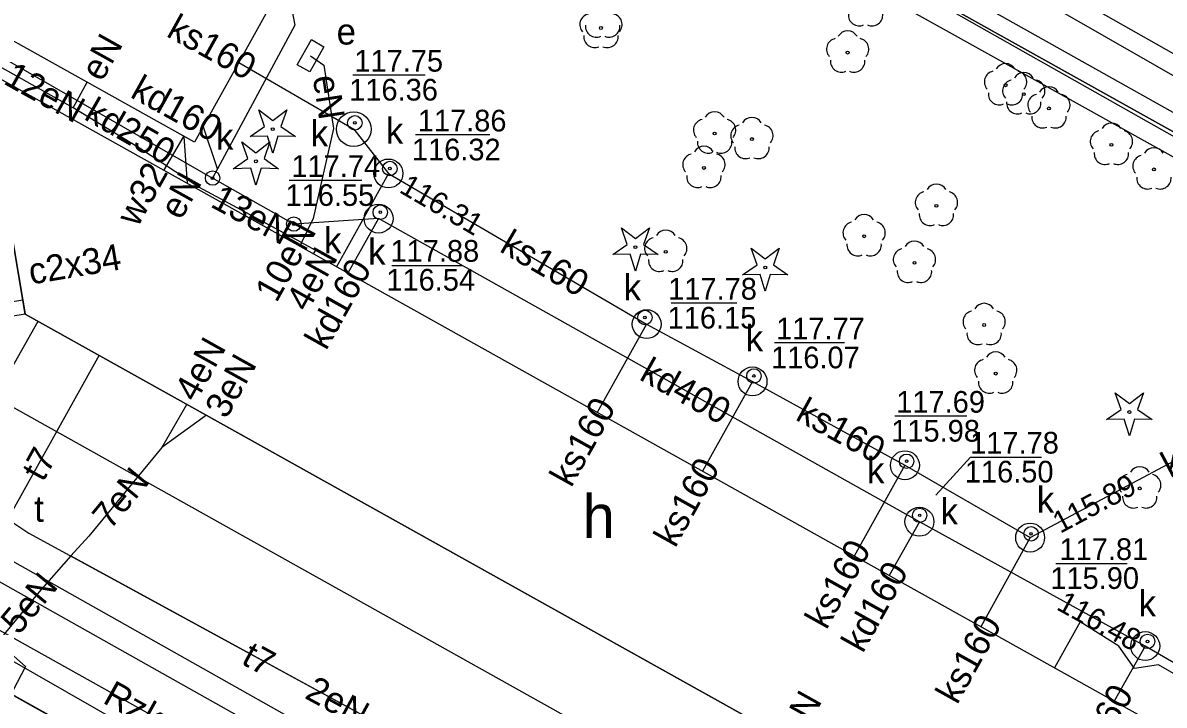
# Model space of a CAD drawing. Extents: x 6434771 to 6436222, y 5663454 to 5664782.
# Drawn here: x 6435316.51 to 6435355.97, y 5663773.05 to 5663796.64 of the extents above; entities that cross this region are included whole.
import ezdxf

# ---------------------------------------------------------------- set-up
doc = ezdxf.new("R2010")
doc.units = 0
for name, color, linetype in [('Warstwa 1', 7, 'Continuous'), ('Warstwa 10', 7, 'Continuous'), ('Warstwa 11', 7, 'Continuous'), ('Warstwa 12', 7, 'Continuous'), ('Warstwa 13', 7, 'Continuous'), ('Warstwa 14', 7, 'Continuous'), ('Warstwa 15', 7, 'Continuous'), ('Warstwa 2', 7, 'Continuous'), ('Warstwa 21', 7, 'Continuous'), ('Warstwa 3', 7, 'Continuous'), ('Warstwa 33', 7, 'Continuous'), ('Warstwa 4', 7, 'Continuous'), ('Warstwa 5', 7, 'Continuous'), ('Warstwa 6', 7, 'Continuous'), ('Warstwa 7', 7, 'Continuous'), ('Warstwa 8', 7, 'Continuous'), ('Warstwa 9', 7, 'Continuous')]:
    doc.layers.add(name, color=color, linetype=linetype)

msp = doc.modelspace()

# ---------------------------------------------------------------- linework, layer by layer
at = {"layer": 'Warstwa 1'}
msp.add_line((6435341.096, 5663801.352), (6435379.471, 5663779.947), dxfattribs=at)
msp.add_line((6435341.096, 5663801.352), (6435379.471, 5663779.947), dxfattribs=at)
for points in [[(6435315.15, 5663804.67), (6435325.88, 5663798.7), (6435322.44, 5663792.51), (6435311.73, 5663798.5), (6435312.37, 5663799.67), (6435312.69, 5663800.25), (6435314.19, 5663802.94), (6435314.51, 5663803.52)], [(6435358.6, 5663770.75), (6435353.88, 5663762.28), (6435350.43, 5663764.21), (6435352.9, 5663768.67), (6435349.4, 5663770.61), (6435348.38, 5663768.83), (6435316.59, 5663786.57), (6435315.32, 5663794.07), (6435315.68, 5663794.72)]]:
    msp.add_lwpolyline(points, close=True, dxfattribs=at)
at = {"layer": 'Warstwa 10'}
for points in [[(6435362.27, 5663788.69), (6435362.41, 5663788.96), (6435362.84, 5663789.86), (6435340.58, 5663802.36), (6435337.82, 5663803.9), (6435320.71, 5663813.64), (6435309.18, 5663820.04), (6435307.2, 5663820.8), (6435302.95, 5663823.03), (6435301.33, 5663824.12), (6435299.2, 5663826.42), (6435293.53, 5663831.99), (6435290.73, 5663834.08), (6435287.63, 5663836.01), (6435276.336, 5663842.501)], [(6435277.98, 5663796.72), (6435309.53, 5663779.08), (6435337.54, 5663763.44)]]:
    msp.add_lwpolyline(points, dxfattribs=at)
for points in [[(6435324.365, 5663792.705), (6435324.867, 5663793.052), (6435324.665, 5663793.628), (6435325.15, 5663793.258), (6435325.635, 5663793.628), (6435325.433, 5663793.052), (6435325.935, 5663792.705), (6435325.325, 5663792.719), (6435325.15, 5663792.135), (6435324.975, 5663792.719)], [(6435323.785, 5663791.595), (6435324.287, 5663791.942), (6435324.085, 5663792.518), (6435324.57, 5663792.148), (6435325.055, 5663792.518), (6435324.853, 5663791.942), (6435325.355, 5663791.595), (6435324.745, 5663791.609), (6435324.57, 5663791.025), (6435324.395, 5663791.609)], [(6435336.905, 5663788.625), (6435337.407, 5663788.972), (6435337.205, 5663789.548), (6435337.69, 5663789.178), (6435338.175, 5663789.548), (6435337.973, 5663788.972), (6435338.475, 5663788.625), (6435337.865, 5663788.639), (6435337.69, 5663788.055), (6435337.515, 5663788.639)], [(6435341.395, 5663787.925), (6435341.897, 5663788.272), (6435341.695, 5663788.848), (6435342.18, 5663788.478), (6435342.665, 5663788.848), (6435342.463, 5663788.272), (6435342.965, 5663787.925), (6435342.355, 5663787.939), (6435342.18, 5663787.355), (6435342.005, 5663787.939)], [(6435353.985, 5663782.925), (6435354.487, 5663783.272), (6435354.285, 5663783.848), (6435354.77, 5663783.478), (6435355.255, 5663783.848), (6435355.053, 5663783.272), (6435355.555, 5663782.925), (6435354.945, 5663782.939), (6435354.77, 5663782.355), (6435354.595, 5663782.939)]]:
    msp.add_lwpolyline(points, close=True, dxfattribs=at)
for centre in [(6435325.15, 5663792.96), (6435324.57, 5663791.85), (6435337.69, 5663788.88), (6435342.18, 5663788.18), (6435354.77, 5663783.18)]:
    msp.add_circle(centre, 0.05, dxfattribs=at)
at = {"layer": 'Warstwa 11'}
for centre in [(6435336.5, 5663796.46), (6435345.03, 5663795.61), (6435350.49, 5663794.48), (6435351.12, 5663794.17), (6435351.99, 5663793.68), (6435340.43, 5663792.81), (6435341.72, 5663792.62), (6435354.15, 5663792.42), (6435340.06, 5663791.62), (6435355.62, 5663791.57), (6435348.1, 5663790.31), (6435345.6, 5663789.26), (6435338.74, 5663788.72), (6435347.34, 5663788.34), (6435349.75, 5663786.19), (6435350.15, 5663784.51), (6435355.13, 5663780.54)]:
    msp.add_circle(centre, 0.05, dxfattribs=at)
for centre, start, end in [((6435336.143, 5663796.576), 102.1471, 221.8529), ((6435336.857, 5663796.576), 318.1471, 77.8529), ((6435345.43, 5663796.907), 174.1471, 293.8529), ((6435345.87, 5663796.907), 246.1471, 5.8529), ((6435336.34, 5663796.517), 174.1471, 293.8529), ((6435336.78, 5663796.517), 246.1471, 5.8529), ((6435336.28, 5663796.157), 174.1471, 293.8529), ((6435336.72, 5663796.157), 246.1471, 5.8529), ((6435345.03, 5663795.985), 30.1471, 149.8529), ((6435344.673, 5663795.726), 102.1471, 221.8529), ((6435345.387, 5663795.726), 318.1471, 77.8529), ((6435344.81, 5663795.307), 174.1471, 293.8529), ((6435345.25, 5663795.307), 246.1471, 5.8529), ((6435350.133, 5663794.596), 102.1471, 221.8529), ((6435350.49, 5663794.855), 30.1471, 149.8529), ((6435350.847, 5663794.596), 318.1471, 77.8529), ((6435350.763, 5663794.286), 102.1471, 221.8529), ((6435351.12, 5663794.545), 30.1471, 149.8529), ((6435351.477, 5663794.286), 318.1471, 77.8529), ((6435350.27, 5663794.177), 174.1471, 293.8529), ((6435350.71, 5663794.177), 246.1471, 5.8529), ((6435351.633, 5663793.796), 102.1471, 221.8529), ((6435351.99, 5663794.055), 30.1471, 149.8529), ((6435352.347, 5663793.796), 318.1471, 77.8529), ((6435350.9, 5663793.867), 174.1471, 293.8529), ((6435351.34, 5663793.867), 246.1471, 5.8529), ((6435340.43, 5663793.185), 30.1471, 149.8529), ((6435341.72, 5663792.995), 30.1471, 149.8529), ((6435351.77, 5663793.377), 174.1471, 293.8529), ((6435352.21, 5663793.377), 246.1471, 5.8529), ((6435340.073, 5663792.926), 102.1471, 221.8529), ((6435340.787, 5663792.926), 318.1471, 77.8529), ((6435341.363, 5663792.736), 102.1471, 221.8529), ((6435342.077, 5663792.736), 318.1471, 77.8529), ((6435354.15, 5663792.795), 30.1471, 149.8529), ((6435353.793, 5663792.536), 102.1471, 221.8529), ((6435354.507, 5663792.536), 318.1471, 77.8529), ((6435340.06, 5663791.995), 30.1471, 149.8529), ((6435340.21, 5663792.507), 174.1471, 293.8529), ((6435340.65, 5663792.507), 246.1471, 5.8529), ((6435341.5, 5663792.317), 174.1471, 293.8529), ((6435341.94, 5663792.317), 246.1471, 5.8529), ((6435355.62, 5663791.945), 30.1471, 149.8529), ((6435339.703, 5663791.736), 102.1471, 221.8529), ((6435340.417, 5663791.736), 318.1471, 77.8529), ((6435353.93, 5663792.117), 174.1471, 293.8529), ((6435354.37, 5663792.117), 246.1471, 5.8529), ((6435355.263, 5663791.686), 102.1471, 221.8529), ((6435339.84, 5663791.317), 174.1471, 293.8529), ((6435340.28, 5663791.317), 246.1471, 5.8529), ((6435348.1, 5663790.685), 30.1471, 149.8529), ((6435355.4, 5663791.267), 174.1471, 293.8529), ((6435355.84, 5663791.267), 246.1471, 5.8529), ((6435347.743, 5663790.426), 102.1471, 221.8529), ((6435348.457, 5663790.426), 318.1471, 77.8529), ((6435345.6, 5663789.635), 30.1471, 149.8529), ((6435347.88, 5663790.007), 174.1471, 293.8529), ((6435348.32, 5663790.007), 246.1471, 5.8529), ((6435338.74, 5663789.095), 30.1471, 149.8529), ((6435345.243, 5663789.376), 102.1471, 221.8529), ((6435345.957, 5663789.376), 318.1471, 77.8529), ((6435338.383, 5663788.836), 102.1471, 221.8529), ((6435339.097, 5663788.836), 318.1471, 77.8529), ((6435347.34, 5663788.715), 30.1471, 149.8529), ((6435345.38, 5663788.957), 174.1471, 293.8529), ((6435345.82, 5663788.957), 246.1471, 5.8529), ((6435346.983, 5663788.456), 102.1471, 221.8529), ((6435347.697, 5663788.456), 318.1471, 77.8529), ((6435338.52, 5663788.417), 174.1471, 293.8529), ((6435338.96, 5663788.417), 246.1471, 5.8529), ((6435347.12, 5663788.037), 174.1471, 293.8529), ((6435347.56, 5663788.037), 246.1471, 5.8529), ((6435349.393, 5663786.306), 102.1471, 221.8529), ((6435349.75, 5663786.565), 30.1471, 149.8529), ((6435350.107, 5663786.306), 318.1471, 77.8529), ((6435349.53, 5663785.887), 174.1471, 293.8529), ((6435349.97, 5663785.887), 246.1471, 5.8529), ((6435350.15, 5663784.885), 30.1471, 149.8529), ((6435349.793, 5663784.626), 102.1471, 221.8529), ((6435350.507, 5663784.626), 318.1471, 77.8529), ((6435349.93, 5663784.207), 174.1471, 293.8529), ((6435350.37, 5663784.207), 246.1471, 5.8529), ((6435355.13, 5663780.915), 30.1471, 149.8529), ((6435354.773, 5663780.656), 102.1471, 221.8529), ((6435355.487, 5663780.656), 318.1471, 77.8529), ((6435354.91, 5663780.237), 174.1471, 293.8529), ((6435355.35, 5663780.237), 246.1471, 5.8529)]:
    msp.add_arc(centre, 0.375, start, end, dxfattribs=at)
at = {"layer": 'Warstwa 12'}
for points in [[(6435276.308, 5663840.167), (6435285.47, 5663834.8), (6435286.134, 5663834.744), (6435286.62, 5663834.35), (6435323.25, 5663813.89), (6435323.79, 5663813.12), (6435324.94, 5663813.03), (6435344.71, 5663802.06), (6435345.376, 5663801.99), (6435345.82, 5663801.51), (6435374.05, 5663785.53), (6435381.33, 5663787.82), (6435417.36, 5663768.01), (6435438.98, 5663755.98), (6435463.27, 5663743.33), (6435463.498, 5663743.152), (6435463.77, 5663743.07), (6435464.82, 5663742.52), (6435490.42, 5663730.15), (6435500.39, 5663725.18)], [(6435276.296, 5663839.122), (6435282.733, 5663835.528), (6435283.155, 5663835.293), (6435283.578, 5663835.058), (6435339.95, 5663804.176), (6435373.154, 5663785.164), (6435373.6, 5663784.903), (6435374.09, 5663784.842), (6435381.569, 5663787.202), (6435381.966, 5663786.947), (6435382.363, 5663786.692), (6435416.468, 5663767.82), (6435452.468, 5663747.664), (6435497.181, 5663726.003), (6435502.116, 5663724.694), (6435541.028, 5663706.294), (6435541.516, 5663706.079), (6435555.51, 5663699.69), (6435571.692, 5663693.874), (6435578.552, 5663690.422)], [(6435301.381, 5663814.818), (6435304.531, 5663813.026), (6435312.56, 5663808.528), (6435317.022, 5663805.997), (6435322.544, 5663803.492), (6435325.031, 5663802.332), (6435326.182, 5663801.779), (6435327.709, 5663801.276), (6435328.664, 5663800.945), (6435329.709, 5663800.582), (6435331.487, 5663800.019), (6435332.294, 5663800.009), (6435333.884, 5663800.34), (6435334.816, 5663800.546), (6435336.575, 5663801.467), (6435337.956, 5663802.205), (6435340.361, 5663800.883), (6435352.831, 5663793.927), (6435371.59, 5663783.486), (6435371.373, 5663781.121), (6435370.67, 5663774.08)], [(6435326.46, 5663795.5), (6435326.92, 5663795.17), (6435327.25, 5663792.98), (6435326.55, 5663789.87), (6435326.15, 5663789.04)], [(6435318.25, 5663793.7), (6435315.69, 5663795.13), (6435314.44, 5663795.28)], [(6435318.25, 5663793.7), (6435318.728, 5663794.586)], [(6435326.15, 5663789.04), (6435322.6, 5663790.96), (6435320.54, 5663792.3), (6435318.25, 5663793.7)], [(6435294.655, 5663789.682), (6435296.51, 5663791.015), (6435297.58, 5663792.845), (6435315.085, 5663782.87), (6435317.04, 5663786.319)], [(6435321.383, 5663791.535), (6435322.081, 5663792.711)], [(6435322.08, 5663792.711), (6435322.19, 5663791.084)], [(6435427.17, 5663739.193), (6435426.34, 5663739.17), (6435421.79, 5663741.74), (6435415.76, 5663730.22), (6435403.78, 5663736.47), (6435393.01, 5663741.8), (6435387.55, 5663744.3), (6435376.19, 5663748.47), (6435370.47, 5663750.27), (6435364.67, 5663752.32), (6435359.09, 5663754.45), (6435353.66, 5663756.84), (6435348.17, 5663759.42), (6435342.78, 5663762.07), (6435335.44, 5663765.94), (6435331.63, 5663758.95), (6435324.69, 5663762.75), (6435328.9, 5663769.89), (6435296.25, 5663788.25), (6435294.655, 5663789.682)], [(6435427.17, 5663739.193), (6435426.57, 5663739.84), (6435421.37, 5663742.74), (6435415.39, 5663731.39), (6435403.97, 5663737.3), (6435393.25, 5663742.68), (6435387.83, 5663745.16), (6435382.26, 5663747.43), (6435376.45, 5663749.28), (6435370.72, 5663751.07), (6435365.02, 5663753.03), (6435359.55, 5663755.18), (6435354, 5663757.65), (6435348.62, 5663760.2), (6435343.16, 5663762.85), (6435335.14, 5663767.04), (6435331.28, 5663760.06), (6435325.83, 5663763.09), (6435330, 5663770.22), (6435296.67, 5663789), (6435294.655, 5663789.682)], [(6435326.15, 5663789.04), (6435326.1, 5663788.901)], [(6435326.15, 5663789.04), (6435326.63, 5663788.78), (6435326.55, 5663788.649)], [(6435319.143, 5663785.145), (6435316.11, 5663779.68), (6435315.97, 5663779.49)], [(6435322.185, 5663783.448), (6435321.32, 5663781.95)], [(6435322.861, 5663783.071), (6435321.32, 5663781.95)], [(6435321.32, 5663781.95), (6435318.79, 5663778.89), (6435318.17, 5663778.21)], [(6435315.97, 5663779.49), (6435316.16, 5663779.36), (6435316.72, 5663778.99), (6435340.13, 5663766.23), (6435340.35, 5663766.11)], [(6435318.17, 5663778.21), (6435317.07, 5663776.97), (6435315.85, 5663775.49)], [(6435318.17, 5663778.21), (6435339.91, 5663766.35)], [(6435369.19, 5663765.15), (6435368.95, 5663766.48), (6435368.25, 5663767.34), (6435361.24, 5663771.29), (6435355.78, 5663774.44), (6435354.95, 5663774.31), (6435354.41, 5663775.09), (6435353.07, 5663775.93), (6435352.178, 5663774.337)], [(6435315.85, 5663775.49), (6435315.9, 5663775), (6435316.6, 5663774.38), (6435315.88, 5663772.99), (6435315.09, 5663772.68), (6435314.53, 5663772.02), (6435318.14, 5663769.85), (6435325.12, 5663766.05), (6435331.93, 5663762.4), (6435337.49, 5663759.67), (6435343.3, 5663756.5), (6435346.21, 5663754.18), (6435348.91, 5663752.54), (6435354.99, 5663749.19), (6435360.95, 5663745.72), (6435362.98, 5663745.33)], [(6435347.37, 5663756.69), (6435314.624, 5663775.443)]]:
    msp.add_lwpolyline(points, dxfattribs=at)
at = {"layer": 'Warstwa 14'}
for p, q in [((6435330.424, 5663794.831), (6435327.919, 5663794.831)), ((6435332.657, 5663792.761), (6435330.088, 5663792.761)), ((6435328.228, 5663791.189), (6435325.718, 5663791.189)), ((6435329.272, 5663788.253), (6435331.712, 5663788.253)), ((6435341.198, 5663786.948), (6435338.924, 5663786.948)), ((6435344.922, 5663785.573), (6435342.506, 5663785.573)), ((6435349.148, 5663783.038), (6435346.662, 5663783.038)), ((6435352.233, 5663777.941), (6435354.695, 5663777.941))]:
    msp.add_line(p, q, dxfattribs=at)
msp.add_lwpolyline([(6435348.084, 5663780.313), (6435349.276, 5663781.62), (6435351.738, 5663781.62)], dxfattribs=at)
for centre in [(6435327.99, 5663793.18), (6435329.2, 5663791.6), (6435329.2, 5663791.6), (6435328.87, 5663790.09), (6435325.88, 5663789.68), (6435338.02, 5663786.45), (6435341.79, 5663784.43), (6435347.07, 5663781.48), (6435347.52, 5663779.61), (6435351.37, 5663778.97), (6435351.37, 5663778.97), (6435355.4, 5663775.25), (6435355.4, 5663775.25)]:
    msp.add_circle(centre, 0.045, dxfattribs=at)
at = {"layer": 'Warstwa 15'}
for centre, radius in [((6435327.95, 5663792.96), 0.6), ((6435329.15, 5663791.43), 0.5), ((6435328.81, 5663789.87), 0.5), ((6435338.08, 5663786.22), 0.5), ((6435341.74, 5663784.24), 0.5), ((6435347.01, 5663781.34), 0.5), ((6435347.51, 5663779.39), 0.5), ((6435351.34, 5663778.84), 0.5), ((6435355.32, 5663775.09), 0.5)]:
    msp.add_circle(centre, radius, dxfattribs=at)
at = {"layer": 'Warstwa 2'}
msp.add_line((6435341.026, 5663801.362), (6435372.62, 5663783.46), dxfattribs=at)
msp.add_lwpolyline([(6435338.01, 5663764.27), (6435336.69, 5663761.93), (6435309.59, 5663777.07), (6435277.13, 5663795.19), (6435278.38, 5663797.42)], dxfattribs=at)
at = {"layer": 'Warstwa 21'}
msp.add_lwpolyline([(6435325.998, 5663795.186), (6435326.486, 5663796.058), (6435326.922, 5663795.814), (6435326.434, 5663794.942), (6435325.998, 5663795.186)], dxfattribs=at)
at = {"layer": 'Warstwa 33'}
for p, q in [((6435315.32, 5663794.07), (6435316.59, 5663786.57)), ((6435310.93, 5663786.27), (6435350.43, 5663764.21)), ((6435316.59, 5663786.57), (6435348.38, 5663768.83))]:
    msp.add_line(p, q, dxfattribs=at)
msp.add_lwpolyline([(6435316.097, 5663786.487), (6435316.014, 5663786.98), (6435316.507, 5663787.063), (6435316.59, 5663786.57)], close=True, dxfattribs=at)
at = {"layer": 'Warstwa 4'}
for centre in [(6435327.99, 5663793.18), (6435329.2, 5663791.6), (6435323.07, 5663791.27), (6435328.87, 5663790.09), (6435325.88, 5663789.68), (6435338.02, 5663786.45), (6435341.79, 5663784.43), (6435347.07, 5663781.48), (6435347.52, 5663779.61), (6435351.37, 5663778.97), (6435355.4, 5663775.25)]:
    msp.add_circle(centre, 0.25, dxfattribs=at)
at = {"layer": 'Warstwa 6'}
for points in [[(6435557.624, 5663617.186), (6435560.245, 5663620.878), (6435595.767, 5663670.923), (6435531.111, 5663701.684), (6435473.15, 5663729.463), (6435470.997, 5663730.839), (6435385.94, 5663776.469), (6435383.505, 5663771.998), (6435381.775, 5663772.849), (6435379.415, 5663768.737), (6435374.588, 5663771.455), (6435379.471, 5663779.947), (6435341.096, 5663801.352), (6435284.269, 5663833.48), (6435246.778, 5663854.403), (6435242.169, 5663846.309), (6435237.4, 5663848.916), (6435241.929, 5663857.022), (6435210.691, 5663874.851), (6435202.784, 5663879.266), (6435199.977, 5663874.56), (6435180.355, 5663839.798)], [(6435246.778, 5663854.403), (6435284.269, 5663833.48), (6435341.096, 5663801.352), (6435379.471, 5663779.947)]]:
    msp.add_lwpolyline(points, dxfattribs=at)
for centre in [(6435327.99, 5663793.18), (6435329.2, 5663791.6), (6435323.07, 5663791.27), (6435328.87, 5663790.09), (6435325.88, 5663789.68), (6435338.02, 5663786.45), (6435341.79, 5663784.43), (6435347.07, 5663781.48), (6435347.52, 5663779.61), (6435351.37, 5663778.97), (6435355.4, 5663775.25)]:
    msp.add_circle(centre, 0.045, dxfattribs=at)
at = {"layer": 'Warstwa 7'}
for points in [[(6435286.14, 5663812.96), (6435285.01, 5663810.71), (6435292.68, 5663806.24), (6435303.78, 5663800.09), (6435313.12, 5663794.86), (6435315.57, 5663795.57), (6435323.07, 5663791.27)], [(6435325.601, 5663798.197), (6435325.92, 5663796.56), (6435323.243, 5663791.591)], [(6435323.973, 5663795.268), (6435327.95, 5663792.96), (6435329.15, 5663791.43)], [(6435323.243, 5663791.591), (6435322.748, 5663793.065)], [(6435323.243, 5663791.591), (6435323.07, 5663791.27)], [(6435329.15, 5663791.43), (6435327.351, 5663788.202)], [(6435329.15, 5663791.43), (6435338.08, 5663786.22), (6435341.74, 5663784.24), (6435347.01, 5663781.34), (6435351.34, 5663778.84), (6435363.4, 5663785.26)], [(6435372.32, 5663765.2), (6435355.32, 5663775.09), (6435347.51, 5663779.39), (6435328.81, 5663789.87), (6435325.88, 5663789.68), (6435323.07, 5663791.27)], [(6435328.81, 5663789.87), (6435327.75, 5663787.979)], [(6435338.08, 5663786.22), (6435336.372, 5663783.164)], [(6435341.74, 5663784.24), (6435340.011, 5663781.132)], [(6435347.01, 5663781.34), (6435345.26, 5663778.2)], [(6435347.51, 5663779.39), (6435346.468, 5663777.526)], [(6435351.34, 5663778.84), (6435349.63, 5663775.76)], [(6435355.32, 5663775.09), (6435354.25, 5663773.18)]]:
    msp.add_lwpolyline(points, dxfattribs=at)
at = {"layer": 'Warstwa 8'}
msp.add_line((6435309.59, 5663777.07), (6435336.69, 5663761.93), dxfattribs=at)
at = {"layer": 'Warstwa 9'}
for p, q in [((6435341.475, 5663801.107), (6435372.62, 5663783.46)), ((6435315.32, 5663794.07), (6435316.59, 5663786.57)), ((6435316.59, 5663786.57), (6435348.38, 5663768.83)), ((6435309.59, 5663777.07), (6435336.69, 5663761.93))]:
    msp.add_line(p, q, dxfattribs=at)

# ---------------------------------------------------------------- texts
at = {"layer": 'Warstwa 11'}
msp.add_text('Rzkd100', height=0.9, rotation=330.8201, dxfattribs=at).set_placement((6435319.234, 5663773.146))
at = {"layer": 'Warstwa 13'}
for s, rotation, p in [('eN', 60.7794, (6435319.244, 5663794.567)), ('12eN', 330.8144, (6435315.801, 5663794.552)), ('eN', 278.5664, (6435326.532, 5663794.765)), ('w32', 60.8195, (6435320.479, 5663789.546)), ('eN', 60.8195, (6435321.977, 5663789.784)), ('13eN', 331.5936, (6435322.957, 5663790.299)), ('10eN', 60.8195, (6435325.279, 5663786.931)), ('c2x34', 9.6085, (6435316.791, 5663787.586)), ('4eN', 60.8195, (6435326.349, 5663786.605)), ('4eN', 60.8367, (6435322.49, 5663783.487)), ('3eN', 60.8367, (6435323.548, 5663782.909)), ('t7', 60.9742, (6435317.21, 5663780.735)), ('7eN', 50.4146, (6435319.53, 5663779.079)), ('5eN', 50.5005, (6435316.364, 5663775.441)), ('t7', 331.4045, (6435324.023, 5663774.496)), ('2eN', 331.3873, (6435326.217, 5663773.308)), ('eN', 60.8367, (6435343.419, 5663771.855))]:
    msp.add_text(s, height=0.9, rotation=rotation, dxfattribs=at).set_placement(p)
at = {"layer": 'Warstwa 14'}
for s, p in [('116.36', (6435327.794, 5663793.951)), ('116.32', (6435329.963, 5663791.882)), ('116.55', (6435325.593, 5663790.309)), ('116.54', (6435329.079, 5663787.378)), ('116.15', (6435338.805, 5663786.068)), ('116.07', (6435342.381, 5663784.693)), ('115.98', (6435346.537, 5663782.158)), ('116.50', (6435349.081, 5663780.745)), ('115.90', (6435352.038, 5663777.066))]:
    msp.add_text(s, height=0.75, dxfattribs=at).set_placement(p)
for s, rotation, p in [('116.31', 329.7372, (6435329.487, 5663790.799)), ('115.89', 28.0291, (6435352.377, 5663778.967)), ('116.48', 331.1639, (6435352.211, 5663776.373))]:
    msp.add_text(s, height=0.75, rotation=rotation, dxfattribs=at).set_placement(p)
at = {"layer": 'Warstwa 21'}
msp.add_text('e', height=0.9, dxfattribs=at).set_placement((6435327.359, 5663795.887))
at = {"layer": 'Warstwa 3'}
msp.add_text('h', height=1.5, dxfattribs=at).set_placement((6435335.864, 5663778.821))
at = {"layer": 'Warstwa 5'}
for s, p in [('k', (6435329.062, 5663792.459)), ('k', (6435323.19, 5663792.254)), ('k', (6435326.462, 5663792.37)), ('k', (6435326.925, 5663788.667)), ('k', (6435328.449, 5663788.279)), ('k', (6435337.285, 5663787.04)), ('k', (6435341.506, 5663785.284)), ('k', (6435345.701, 5663780.721)), ('k', (6435351.569, 5663779.7)), ('t', (6435316.903, 5663779.387)), ('k', (6435348.241, 5663779.296)), ('k', (6435355.089, 5663776.117))]:
    msp.add_text(s, height=0.9, dxfattribs=at).set_placement(p)
at = {"layer": 'Warstwa 6'}
for s, p in [('117.75', (6435327.973, 5663794.951)), ('117.86', (6435330.165, 5663792.882)), ('117.74', (6435325.795, 5663791.309)), ('117.88', (6435329.222, 5663788.378)), ('117.78', (6435338.824, 5663787.068)), ('117.77', (6435342.554, 5663785.693)), ('117.69', (6435346.709, 5663783.158)), ('117.78', (6435349.265, 5663781.745)), ('117.81', (6435352.355, 5663778.066))]:
    msp.add_text(s, height=0.75, dxfattribs=at).set_placement(p)
at = {"layer": 'Warstwa 7'}
for s, rotation, p in [('ks160', 330.9347, (6435321.436, 5663796.192)), ('kd160', 330.9347, (6435320.185, 5663794.087)), ('kd250', 330.1727, (6435318.587, 5663793.322)), ('ks160', 329.7372, (6435332.954, 5663788.754)), ('kd160', 60.8195, (6435326.996, 5663785.283)), ('kd400', 330.7342, (6435337.788, 5663784.323)), ('ks160', 60.8195, (6435335.47, 5663780.541)), ('ks160', 331.1753, (6435343.185, 5663782.932)), ('ks160', 28.0291, (6435356.181, 5663780.888)), ('ks160', 60.8195, (6435339.067, 5663778.455)), ('ks160', 60.8195, (6435344.295, 5663775.623)), ('kd160', 60.8195, (6435345.553, 5663774.812)), ('ks160', 60.8195, (6435348.815, 5663773.037)), ('kd160', 60.8195, (6435353.341, 5663770.565))]:
    msp.add_text(s, height=0.9, rotation=rotation, dxfattribs=at).set_placement(p)

doc.saveas('drawing.dxf')
